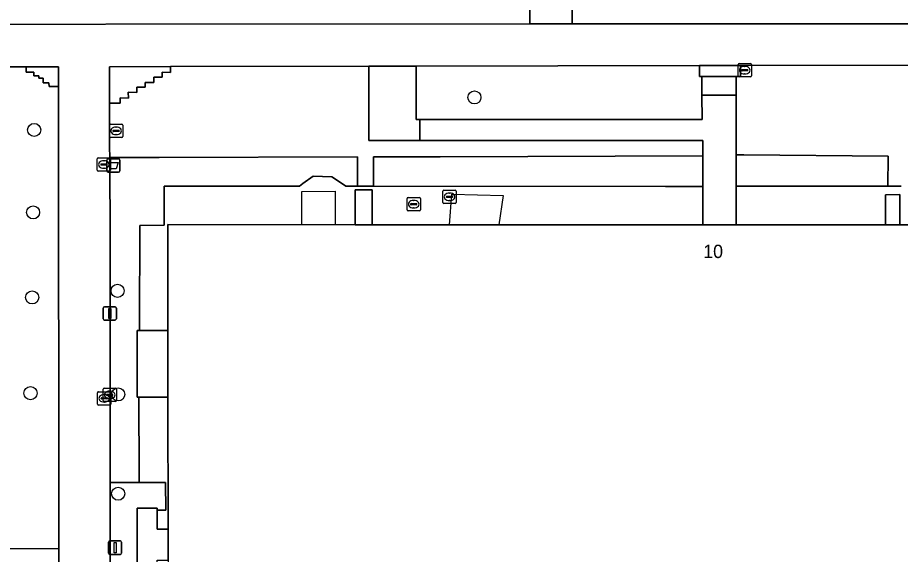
# Model space of a CAD drawing. Extents: x 161477 to 163040, y 383680 to 384871.
# Drawn here: x 161860.2 to 161926.3, y 384151.2 to 384191.4 of the extents above; entities that cross this region are included whole.
import ezdxf

# ---------------------------------------------------------------- set-up
doc = ezdxf.new("R2010")
doc.units = 0
for name, color, linetype in [('IMGEO_Afvalbak', 7, 'Continuous'), ('IMGEO_Boom', 7, 'Continuous'), ('IMGEO_Groenvoorziening', 7, 'Continuous'), ('IMGEO_Hek', 7, 'Continuous'), ('IMGEO_Kolk', 7, 'Continuous'), ('IMGEO_Lichtmast', 7, 'Continuous'), ('IMGEO_Pand', 7, 'Continuous'), ('IMGEO_Pand_nummerreeks', 7, 'Continuous'), ('IMGEO_Rioolput', 7, 'Continuous'), ('IMGEO_Terreindeel_onvherhard', 7, 'Continuous'), ('IMGEO_Voetpad_gesloten', 7, 'Continuous'), ('IMGEO_Voetpad_halfverhard', 7, 'Continuous'), ('IMGEO_Voetpad_op_trap', 7, 'Continuous'), ('IMGEO_Voetpad_open', 7, 'Continuous')]:
    doc.layers.add(name, color=color, linetype=linetype)

msp = doc.modelspace()

# ---------------------------------------------------------------- linework, layer by layer
at = {"layer": 'IMGEO_Afvalbak'}
for p, q in [((161866.835, 384179.91), (161866.835, 384180.71)), ((161866.835, 384180.71), (161866.835, 384179.91)), ((161866.935, 384180.81), (161867.725, 384180.81)), ((161867.725, 384180.81), (161866.935, 384180.81)), ((161867.825, 384180.71), (161867.825, 384179.91)), ((161867.825, 384179.91), (161867.825, 384180.71)), ((161867.725, 384179.81), (161866.935, 384179.81)), ((161866.935, 384179.81), (161867.725, 384179.81))]:
    msp.add_line(p, q, dxfattribs=at)
msp.add_lwpolyline([(161866.978, 384180.524), (161867.682, 384180.524), (161867.533, 384180.054), (161867.127, 384180.054), (161866.978, 384180.524)], dxfattribs=at)
for centre, start, end in [((161866.935, 384180.71), 90, 180), ((161866.935, 384180.71), 90, 180), ((161867.725, 384180.71), 0, 90), ((161867.725, 384180.71), 360, 90), ((161866.935, 384179.91), 180, 270), ((161866.935, 384179.91), 180, 270), ((161867.725, 384179.91), 270, 0), ((161867.725, 384179.91), 270, 0)]:
    msp.add_arc(centre, 0.1, start, end, dxfattribs=at)
at = {"layer": 'IMGEO_Boom'}
for centre in [(161894.4, 384185.41), (161861.392, 384182.972), (161861.316, 384176.797), (161867.643, 384170.917), (161861.243, 384170.422), (161861.119, 384163.251), (161867.69, 384163.158), (161867.69, 384155.716)]:
    msp.add_circle(centre, 0.489, dxfattribs=at)
at = {"layer": 'IMGEO_Groenvoorziening'}
for points in [[(161959.935, 384200.23), (161959.929, 384200.954), (161957.522, 384200.994), (161947.488, 384200.994), (161945.032, 384200.994), (161928.988, 384200.994), (161928.988, 384218.997), (161901.724, 384218.997), (161901.724, 384190.932), (161937.431, 384190.919), (161950.369, 384190.922), (161959.829, 384191.078), (161959.943, 384199.331)], [(161898.56, 384203.307), (161831.783, 384203.307), (161831.783, 384192.925), (161832.53, 384192.925), (161832.53, 384192.317), (161833.278, 384192.317), (161833.278, 384191.865), (161834.073, 384191.865), (161834.073, 384191.46), (161834.915, 384191.46), (161834.916, 384190.882), (161898.56, 384190.919)], [(161886.491, 384187.746), (161871.621, 384187.719), (161871.622, 384187.289), (161870.989, 384187.298), (161870.979, 384186.925), (161870.359, 384186.923), (161870.354, 384186.531), (161869.725, 384186.534), (161869.723, 384186.17), (161869.097, 384186.168), (161869.103, 384185.781), (161868.448, 384185.792), (161868.469, 384185.36), (161867.843, 384185.37), (161867.839, 384184.989), (161867.046, 384184.991), (161867.053, 384181.699), (161867.055, 384180.903), (161870.771, 384180.913), (161885.628, 384180.952), (161885.628, 384178.755), (161886.844, 384178.76), (161886.844, 384180.955), (161891.838, 384180.969), (161911.527, 384181.021), (161911.527, 384182.179), (161890.318, 384182.179), (161886.493, 384182.179)], [(161911.445, 384186.981), (161911.288, 384186.981), (161911.288, 384187.79), (161890.029, 384187.752), (161890.031, 384183.761), (161890.321, 384183.757), (161911.485, 384183.749), (161911.462, 384185.585)], [(161911.527, 384181.021), (161891.838, 384180.969), (161886.844, 384180.955), (161886.844, 384178.76), (161908.738, 384178.74), (161911.526, 384178.737)], [(161925.428, 384181.007), (161914.591, 384181.113), (161914.03, 384181.119), (161914.029, 384178.754), (161917.259, 384178.754), (161925.397, 384178.753)], [(161869.117, 384167.939), (161869.285, 384167.939), (161869.286, 384168.262), (161869.315, 384175.802), (161871.142, 384175.827), (161871.142, 384178.767), (161881.283, 384178.758), (161881.537, 384178.948), (161882.306, 384179.521), (161883.718, 384179.459), (161884.289, 384179.076), (161884.766, 384178.755), (161885.628, 384178.755), (161885.628, 384180.952), (161870.771, 384180.913), (161867.055, 384180.903), (161867.055, 384180.764), (161867.078, 384179.395), (161867.081, 384176.171), (161867.101, 384156.591), (161867.101, 384156.554), (161869.229, 384156.554), (161869.266, 384156.554), (161869.263, 384157.915), (161869.253, 384162.172), (161869.251, 384162.956), (161869.107, 384162.957)]]:
    msp.add_lwpolyline(points, close=True, dxfattribs=at)
for points in [[(161856.034, 384151.593), (161863.239, 384151.611), (161863.207, 384185.898), (161863.207, 384186.237), (161862.507, 384186.237), (161862.492, 384186.514), (161862.065, 384186.514), (161862.065, 384186.863), (161861.737, 384186.863), (161861.737, 384187.027), (161861.378, 384187.027), (161861.378, 384187.314), (161860.783, 384187.314), (161860.783, 384187.71), (161852.453, 384187.71)], [(161942.475, 384187.845), (161914.35, 384187.795), (161914.35, 384186.981), (161914.032, 384186.981), (161914.032, 384185.585), (161914.03, 384181.119), (161914.591, 384181.113), (161925.428, 384181.007), (161925.397, 384178.753), (161926.399, 384178.767)]]:
    msp.add_lwpolyline(points, dxfattribs=at)
at = {"layer": 'IMGEO_Hek'}
for points in [[(161881.458, 384178.371), (161883.959, 384178.376)], [(161881.458, 384175.876), (161881.458, 384178.371)], [(161883.959, 384178.376), (161883.959, 384175.876)], [(161892.524, 384175.874), (161892.708, 384178.17)], [(161892.708, 384178.17), (161896.552, 384178.063)], [(161896.552, 384178.063), (161896.239, 384175.874)]]:
    msp.add_lwpolyline(points, dxfattribs=at)
at = {"layer": 'IMGEO_Kolk'}
for p, q in [((161914.169, 384187.024), (161914.169, 384187.876)), ((161914.244, 384187.95), (161915.096, 384187.95)), ((161914.657, 384187.73), (161914.682, 384187.73)), ((161915.17, 384187.876), (161915.17, 384187.024)), ((161915.096, 384186.95), (161914.244, 384186.95)), ((161914.428, 384187.444), (161914.428, 384187.456)), ((161914.866, 384187.407), (161914.468, 384187.407)), ((161914.471, 384187.493), (161914.869, 384187.493)), ((161914.68, 384187.17), (161914.655, 384187.17)), ((161914.912, 384187.456), (161914.912, 384187.444)), ((161867.036, 384182.483), (161867.036, 384183.335)), ((161867.111, 384183.409), (161867.963, 384183.409)), ((161867.338, 384182.952), (161867.736, 384182.952)), ((161867.524, 384183.189), (161867.549, 384183.189)), ((161868.037, 384183.335), (161868.037, 384182.483)), ((161867.963, 384182.409), (161867.111, 384182.409)), ((161867.295, 384182.903), (161867.295, 384182.915)), ((161867.733, 384182.866), (161867.335, 384182.866)), ((161867.547, 384182.629), (161867.522, 384182.629)), ((161867.779, 384182.915), (161867.779, 384182.903)), ((161866.121, 384179.958), (161866.121, 384180.81)), ((161866.196, 384180.884), (161867.048, 384180.884)), ((161866.38, 384180.378), (161866.38, 384180.39)), ((161866.818, 384180.341), (161866.42, 384180.341)), ((161866.423, 384180.427), (161866.821, 384180.427)), ((161866.609, 384180.664), (161866.634, 384180.664)), ((161866.864, 384180.39), (161866.864, 384180.378)), ((161867.122, 384180.81), (161867.122, 384179.958)), ((161867.048, 384179.884), (161866.196, 384179.884)), ((161866.632, 384180.104), (161866.607, 384180.104)), ((161866.147, 384162.433), (161866.147, 384163.285)), ((161866.222, 384163.359), (161867.074, 384163.359)), ((161866.56, 384162.694), (161866.56, 384163.546)), ((161866.635, 384163.62), (161867.487, 384163.62)), ((161866.635, 384163.139), (161866.66, 384163.139)), ((161866.819, 384163.114), (161866.819, 384163.126)), ((161866.862, 384163.163), (161867.26, 384163.163)), ((161867.048, 384163.4), (161867.073, 384163.4)), ((161867.148, 384163.285), (161867.148, 384162.433)), ((161867.303, 384163.126), (161867.303, 384163.114)), ((161867.561, 384163.546), (161867.561, 384162.694)), ((161866.406, 384162.853), (161866.406, 384162.865)), ((161866.844, 384162.816), (161866.446, 384162.816)), ((161866.449, 384162.902), (161866.847, 384162.902)), ((161866.658, 384162.579), (161866.633, 384162.579)), ((161867.487, 384162.62), (161866.635, 384162.62)), ((161867.257, 384163.077), (161866.859, 384163.077)), ((161866.89, 384162.865), (161866.89, 384162.853)), ((161867.071, 384162.84), (161867.046, 384162.84)), ((161867.074, 384162.359), (161866.222, 384162.359))]:
    msp.add_line(p, q, dxfattribs=at)
for points in [[(161914.169, 384187.024), (161914.169, 384187.876)], [(161914.244, 384187.95), (161915.096, 384187.95)], [(161915.17, 384187.876), (161915.17, 384187.024)], [(161915.096, 384186.95), (161914.244, 384186.95)], [(161867.036, 384182.483), (161867.036, 384183.335)], [(161867.111, 384183.409), (161867.963, 384183.409)], [(161868.037, 384183.335), (161868.037, 384182.483)], [(161867.963, 384182.409), (161867.111, 384182.409)], [(161866.121, 384179.958), (161866.121, 384180.81)], [(161866.196, 384180.884), (161867.048, 384180.884)], [(161867.122, 384180.81), (161867.122, 384179.958)], [(161867.048, 384179.884), (161866.196, 384179.884)], [(161866.147, 384162.433), (161866.147, 384163.285)], [(161866.222, 384163.359), (161867.074, 384163.359)], [(161866.56, 384162.694), (161866.56, 384163.546)], [(161866.635, 384163.62), (161867.487, 384163.62)], [(161867.148, 384163.285), (161867.148, 384162.433)], [(161867.561, 384163.546), (161867.561, 384162.694)], [(161867.487, 384162.62), (161866.635, 384162.62)], [(161867.074, 384162.359), (161866.222, 384162.359)]]:
    msp.add_lwpolyline(points, dxfattribs=at)
for centre, radius, start, end in [((161914.246, 384187.874), 0.0765, 91.55205, 178.44795), ((161914.246, 384187.874), 0.0765, 91.55205, 178.44795), ((161915.094, 384187.874), 0.0765, 1.55205, 88.44795), ((161915.094, 384187.874), 0.0765, 1.55205, 88.44795), ((161914.246, 384187.026), 0.0765, 181.55205, 268.44795), ((161914.246, 384187.026), 0.0765, 181.55205, 268.44795), ((161914.468, 384187.453), 0.0403, 85.87752, 175.75265), ((161914.465, 384187.443), 0.0366, 178.93798, 274.71019), ((161914.869, 384187.45), 0.043, 264.86636, 352.45326), ((161914.873, 384187.455), 0.0386, 1.73085, 96.63898), ((161915.094, 384187.026), 0.0765, 271.55205, 358.44795), ((161915.094, 384187.026), 0.0765, 271.55205, 358.44795), ((161867.113, 384183.333), 0.0765, 91.55205, 178.44795), ((161867.113, 384183.333), 0.0765, 91.55205, 178.44795), ((161867.335, 384182.912), 0.0403, 85.87752, 175.75265), ((161867.74, 384182.914), 0.0386, 1.73085, 96.63898), ((161867.961, 384183.333), 0.0765, 1.55205, 88.44795), ((161867.961, 384183.333), 0.0765, 1.55205, 88.44795), ((161867.113, 384182.485), 0.0765, 181.55205, 268.44795), ((161867.113, 384182.485), 0.0765, 181.55205, 268.44795), ((161867.332, 384182.902), 0.0366, 178.93798, 274.71019), ((161867.736, 384182.909), 0.043, 264.86636, 352.45326), ((161867.961, 384182.485), 0.0765, 271.55205, 358.44795), ((161867.961, 384182.485), 0.0765, 271.55205, 358.44795), ((161866.198, 384180.808), 0.0765, 91.55205, 178.44795), ((161866.198, 384180.808), 0.0765, 91.55205, 178.44795), ((161866.42, 384180.387), 0.0403, 85.87752, 175.75265), ((161866.417, 384180.377), 0.0366, 178.93798, 274.71019), ((161866.821, 384180.384), 0.043, 264.86636, 352.45326), ((161866.825, 384180.389), 0.0386, 1.73085, 96.63898), ((161867.046, 384180.808), 0.0765, 1.55205, 88.44795), ((161867.046, 384180.808), 0.0765, 1.55205, 88.44795), ((161866.198, 384179.96), 0.0765, 181.55205, 268.44795), ((161866.198, 384179.96), 0.0765, 181.55205, 268.44795), ((161867.046, 384179.96), 0.0765, 271.55205, 358.44795), ((161867.046, 384179.96), 0.0765, 271.55205, 358.44795), ((161866.224, 384163.283), 0.0765, 91.55205, 178.44795), ((161866.224, 384163.283), 0.0765, 91.55205, 178.44795), ((161866.637, 384163.544), 0.0765, 91.55205, 178.44795), ((161866.637, 384163.544), 0.0765, 91.55205, 178.44795), ((161866.859, 384163.123), 0.0403, 85.87752, 175.75265), ((161866.856, 384163.113), 0.0366, 178.93798, 274.71019), ((161867.072, 384163.283), 0.0765, 1.55205, 88.44795), ((161867.072, 384163.283), 0.0765, 1.55205, 88.44795), ((161867.26, 384163.12), 0.043, 264.86636, 352.45326), ((161867.264, 384163.125), 0.0386, 1.73085, 96.63898), ((161867.485, 384163.544), 0.0765, 1.55205, 88.44795), ((161867.485, 384163.544), 0.0765, 1.55205, 88.44795), ((161866.224, 384162.435), 0.0765, 181.55205, 268.44795), ((161866.224, 384162.435), 0.0765, 181.55205, 268.44795), ((161866.446, 384162.862), 0.0403, 85.87752, 175.75265), ((161866.443, 384162.852), 0.0366, 178.93798, 274.71019), ((161866.637, 384162.696), 0.0765, 181.55205, 268.44795), ((161866.637, 384162.696), 0.0765, 181.55205, 268.44795), ((161866.847, 384162.859), 0.043, 264.86636, 352.45326), ((161866.851, 384162.864), 0.0386, 1.73085, 96.63898), ((161867.072, 384162.435), 0.0765, 271.55205, 358.44795), ((161867.072, 384162.435), 0.0765, 271.55205, 358.44795), ((161867.485, 384162.696), 0.0765, 271.55205, 358.44795), ((161867.485, 384162.696), 0.0765, 271.55205, 358.44795)]:
    msp.add_arc(centre, radius, start, end, dxfattribs=at)
for centre, major_axis, ratio, start_param, end_param in [((161914.656, 384187.45), (-0.387, 0.002), 0.722429, 4.712389, 7.853982), ((161914.681, 384187.45), (-0.39, 0.002), 0.717154, 1.570796, 4.712389), ((161867.523, 384182.909), (-0.387, 0.002), 0.722429, 4.712389, 7.853982), ((161867.548, 384182.909), (-0.39, 0.002), 0.717154, 1.570796, 4.712389), ((161866.608, 384180.384), (-0.387, 0.002), 0.722429, 4.712389, 7.853982), ((161866.633, 384180.384), (-0.39, 0.002), 0.717154, 1.570796, 4.712389), ((161866.634, 384162.859), (-0.387, 0.002), 0.722429, 4.712389, 7.853982), ((161866.659, 384162.859), (-0.39, 0.002), 0.717154, 1.570796, 4.712389), ((161867.047, 384163.12), (-0.387, 0.002), 0.722429, 4.712389, 7.853982), ((161867.072, 384163.12), (-0.39, 0.002), 0.717154, 1.570796, 4.712389)]:
    msp.add_ellipse(centre, major_axis=major_axis, ratio=ratio, start_param=start_param, end_param=end_param, dxfattribs=at)
at = {"layer": 'IMGEO_Lichtmast'}
for p, q in [((161866.665, 384169.73), (161867.455, 384169.73)), ((161867.455, 384169.73), (161866.665, 384169.73)), ((161866.565, 384168.83), (161866.565, 384169.63)), ((161866.565, 384169.63), (161866.565, 384168.83)), ((161867.555, 384169.63), (161867.555, 384168.83)), ((161867.555, 384168.83), (161867.555, 384169.63)), ((161867.455, 384168.73), (161866.665, 384168.73)), ((161866.665, 384168.73), (161867.455, 384168.73)), ((161866.962, 384151.272), (161866.962, 384152.072)), ((161866.962, 384152.072), (161866.962, 384151.272)), ((161867.062, 384152.172), (161867.852, 384152.172)), ((161867.852, 384152.172), (161867.062, 384152.172)), ((161867.952, 384152.072), (161867.952, 384151.272)), ((161867.952, 384151.272), (161867.952, 384152.072)), ((161867.852, 384151.172), (161867.062, 384151.172)), ((161867.062, 384151.172), (161867.852, 384151.172))]:
    msp.add_line(p, q, dxfattribs=at)
for points in [[(161866.985, 384169.605), (161867.135, 384169.605), (161867.135, 384168.855), (161866.985, 384168.855), (161866.985, 384169.605)], [(161867.382, 384152.047), (161867.532, 384152.047), (161867.532, 384151.297), (161867.382, 384151.297), (161867.382, 384152.047)]]:
    msp.add_lwpolyline(points, dxfattribs=at)
for centre, start, end in [((161866.665, 384169.63), 90, 180), ((161866.665, 384169.63), 90, 180), ((161867.455, 384169.63), 0, 90), ((161867.455, 384169.63), 360, 90), ((161866.665, 384168.83), 180, 270), ((161866.665, 384168.83), 180, 270), ((161867.455, 384168.83), 270, 0), ((161867.455, 384168.83), 270, 0), ((161867.062, 384152.072), 90, 180), ((161867.062, 384152.072), 90, 180), ((161867.852, 384152.072), 0, 90), ((161867.852, 384152.072), 360, 90), ((161867.062, 384151.272), 180, 270), ((161867.062, 384151.272), 180, 270), ((161867.852, 384151.272), 270, 0), ((161867.852, 384151.272), 270, 0)]:
    msp.add_arc(centre, 0.1, start, end, dxfattribs=at)
at = {"layer": 'IMGEO_Pand'}
msp.add_lwpolyline([(161945.027, 384175.873), (161926.299, 384175.874), (161925.232, 384175.874), (161914.028, 384175.874), (161911.525, 384175.874), (161886.732, 384175.875), (161885.455, 384175.875), (161871.412, 384175.876), (161871.419, 384168.026), (161871.419, 384167.933), (161871.423, 384163.067), (161871.423, 384162.958), (161871.432, 384153.064), (161871.434, 384150.746), (161871.439, 384144.431), (161871.441, 384142.039), (161871.446, 384136.601), (161876.803, 384136.603), (161879.273, 384136.604), (161919.889, 384136.62), (161935.366, 384136.609)], dxfattribs=at)
at = {"layer": 'IMGEO_Rioolput'}
for p, q in [((161892.039, 384177.534), (161892.039, 384178.386)), ((161892.114, 384178.46), (161892.966, 384178.46)), ((161893.04, 384178.386), (161893.04, 384177.534)), ((161889.349, 384176.984), (161889.349, 384177.836)), ((161889.424, 384177.91), (161890.276, 384177.91)), ((161889.837, 384177.69), (161889.862, 384177.69)), ((161890.35, 384177.836), (161890.35, 384176.984)), ((161892.298, 384177.954), (161892.298, 384177.966)), ((161892.736, 384177.917), (161892.338, 384177.917)), ((161892.341, 384178.003), (161892.739, 384178.003)), ((161892.55, 384177.68), (161892.525, 384177.68)), ((161892.527, 384178.24), (161892.552, 384178.24)), ((161892.782, 384177.966), (161892.782, 384177.954)), ((161889.608, 384177.404), (161889.608, 384177.416)), ((161890.046, 384177.367), (161889.648, 384177.367)), ((161889.651, 384177.453), (161890.049, 384177.453)), ((161889.86, 384177.13), (161889.835, 384177.13)), ((161890.092, 384177.416), (161890.092, 384177.404)), ((161892.966, 384177.46), (161892.114, 384177.46)), ((161890.276, 384176.91), (161889.424, 384176.91))]:
    msp.add_line(p, q, dxfattribs=at)
for points in [[(161892.039, 384177.534), (161892.039, 384178.386)], [(161892.114, 384178.46), (161892.966, 384178.46)], [(161893.04, 384178.386), (161893.04, 384177.534)], [(161889.349, 384176.984), (161889.349, 384177.836)], [(161889.424, 384177.91), (161890.276, 384177.91)], [(161890.35, 384177.836), (161890.35, 384176.984)], [(161892.966, 384177.46), (161892.114, 384177.46)], [(161890.276, 384176.91), (161889.424, 384176.91)]]:
    msp.add_lwpolyline(points, dxfattribs=at)
for centre, radius, start, end in [((161892.116, 384178.384), 0.0765, 91.55205, 178.44795), ((161892.116, 384178.384), 0.0765, 91.55205, 178.44795), ((161892.964, 384178.384), 0.0765, 1.55205, 88.44795), ((161892.964, 384178.384), 0.0765, 1.55205, 88.44795), ((161889.426, 384177.834), 0.0765, 91.55205, 178.44795), ((161889.426, 384177.834), 0.0765, 91.55205, 178.44795), ((161890.274, 384177.834), 0.0765, 1.55205, 88.44795), ((161890.274, 384177.834), 0.0765, 1.55205, 88.44795), ((161892.338, 384177.963), 0.0403, 85.87752, 175.75265), ((161892.335, 384177.953), 0.0366, 178.93798, 274.71019), ((161892.739, 384177.96), 0.043, 264.86636, 352.45326), ((161892.743, 384177.965), 0.0386, 1.73085, 96.63898), ((161889.648, 384177.413), 0.0403, 85.87752, 175.75265), ((161889.645, 384177.403), 0.0366, 178.93798, 274.71019), ((161890.049, 384177.41), 0.043, 264.86636, 352.45326), ((161890.053, 384177.415), 0.0386, 1.73085, 96.63898), ((161892.116, 384177.536), 0.0765, 181.55205, 268.44795), ((161892.116, 384177.536), 0.0765, 181.55205, 268.44795), ((161892.964, 384177.536), 0.0765, 271.55205, 358.44795), ((161892.964, 384177.536), 0.0765, 271.55205, 358.44795), ((161889.426, 384176.986), 0.0765, 181.55205, 268.44795), ((161889.426, 384176.986), 0.0765, 181.55205, 268.44795), ((161890.274, 384176.986), 0.0765, 271.55205, 358.44795), ((161890.274, 384176.986), 0.0765, 271.55205, 358.44795)]:
    msp.add_arc(centre, radius, start, end, dxfattribs=at)
for centre, major_axis, ratio, start_param, end_param in [((161889.836, 384177.41), (-0.387, 0.002), 0.722429, 4.712389, 7.853982), ((161889.861, 384177.41), (-0.39, 0.002), 0.717154, 1.570796, 4.712389), ((161892.526, 384177.96), (-0.387, 0.002), 0.722429, 4.712389, 7.853982), ((161892.551, 384177.96), (-0.39, 0.002), 0.717154, 1.570796, 4.712389)]:
    msp.add_ellipse(centre, major_axis=major_axis, ratio=ratio, start_param=start_param, end_param=end_param, dxfattribs=at)
at = {"layer": 'IMGEO_Terreindeel_onvherhard'}
for points in [[(161911.526, 384178.737), (161908.738, 384178.74), (161886.844, 384178.76), (161885.628, 384178.755), (161884.766, 384178.755), (161884.289, 384179.076), (161883.718, 384179.459), (161882.306, 384179.521), (161881.537, 384178.948), (161881.283, 384178.758), (161871.142, 384178.767), (161871.142, 384175.827), (161869.315, 384175.802), (161869.286, 384168.262), (161869.285, 384167.939), (161871.419, 384167.933), (161871.419, 384168.026), (161871.412, 384175.876), (161885.455, 384175.875), (161885.457, 384176.515), (161885.465, 384178.486), (161886.742, 384178.486), (161886.735, 384176.518), (161886.732, 384175.875), (161911.525, 384175.874)], [(161871.423, 384162.958), (161870.207, 384162.952), (161869.251, 384162.956), (161869.253, 384162.172), (161869.263, 384157.915), (161869.266, 384156.554), (161871.252, 384156.555), (161871.253, 384154.482), (161870.611, 384154.478), (161870.614, 384153.062), (161871.432, 384153.064)]]:
    msp.add_lwpolyline(points, close=True, dxfattribs=at)
msp.add_lwpolyline([(161926.399, 384178.767), (161925.397, 384178.753), (161917.259, 384178.754), (161914.029, 384178.754), (161914.028, 384175.874), (161925.232, 384175.874), (161925.233, 384176.583), (161925.235, 384178.123), (161926.302, 384178.134), (161926.3, 384176.585), (161926.299, 384175.874), (161945.027, 384175.873)], dxfattribs=at)
at = {"layer": 'IMGEO_Voetpad_gesloten'}
msp.add_lwpolyline([(161871.419, 384167.933), (161869.285, 384167.939), (161869.117, 384167.939), (161869.107, 384162.957), (161869.251, 384162.956), (161870.207, 384162.952), (161871.423, 384162.958), (161871.423, 384163.067)], close=True, dxfattribs=at)
at = {"layer": 'IMGEO_Voetpad_halfverhard'}
for points in [[(161863.207, 384187.71), (161860.783, 384187.71), (161860.783, 384187.314), (161861.378, 384187.314), (161861.378, 384187.027), (161861.737, 384187.027), (161861.737, 384186.863), (161862.065, 384186.863), (161862.065, 384186.514), (161862.492, 384186.514), (161862.507, 384186.237), (161863.207, 384186.237)], [(161863.239, 384151.611), (161856.034, 384151.593), (161855.992, 384155.169), (161846.414, 384155.222), (161846.399, 384145.662), (161855.978, 384145.626), (161856.031, 384149.227), (161863.247, 384149.196)]]:
    msp.add_lwpolyline(points, close=True, dxfattribs=at)
at = {"layer": 'IMGEO_Voetpad_op_trap'}
for points in [[(161914.032, 384186.981), (161913.96, 384186.981), (161911.445, 384186.981), (161911.462, 384185.585), (161914.032, 384185.585)], [(161886.742, 384178.486), (161885.465, 384178.486), (161885.457, 384176.515), (161885.455, 384175.875), (161886.732, 384175.875), (161886.735, 384176.518)], [(161926.302, 384178.134), (161925.235, 384178.123), (161925.233, 384176.583), (161925.232, 384175.874), (161926.299, 384175.874), (161926.3, 384176.585)]]:
    msp.add_lwpolyline(points, close=True, dxfattribs=at)
at = {"layer": 'IMGEO_Voetpad_open'}
for points in [[(161898.56, 384203.307), (161898.56, 384190.919), (161901.724, 384190.932), (161901.724, 384218.997)], [(161959.943, 384199.331), (161959.829, 384191.078), (161950.369, 384190.922), (161937.431, 384190.919), (161901.724, 384190.932), (161898.56, 384190.919), (161834.916, 384190.882)], [(161852.453, 384187.71), (161860.783, 384187.71), (161863.207, 384187.71), (161863.207, 384186.237), (161863.207, 384185.898), (161863.239, 384151.611), (161863.247, 384149.196), (161863.257, 384144.435), (161863.262, 384142.045), (161863.289, 384128.521), (161844.945, 384128.623)], [(161858.546, 384119.067), (161867.138, 384119.099), (161867.115, 384142.042), (161867.113, 384144.433), (161867.101, 384156.554), (161867.101, 384156.591), (161867.081, 384176.171), (161867.078, 384179.395), (161867.055, 384180.764), (161867.055, 384180.903), (161867.053, 384181.699), (161867.046, 384184.991), (161867.041, 384187.711), (161871.621, 384187.719), (161886.491, 384187.746), (161890.029, 384187.752), (161911.288, 384187.79), (161911.343, 384187.79), (161914.35, 384187.795), (161942.475, 384187.845)], [(161869.141, 384144.432), (161869.122, 384154.637), (161870.61, 384154.629), (161870.611, 384154.478), (161871.253, 384154.482), (161871.252, 384156.555), (161869.266, 384156.554), (161869.229, 384156.554), (161867.101, 384156.554), (161867.113, 384144.433)]]:
    msp.add_lwpolyline(points, dxfattribs=at)
for points in [[(161870.359, 384186.923), (161870.979, 384186.925), (161870.989, 384187.298), (161871.622, 384187.289), (161871.621, 384187.719), (161867.041, 384187.711), (161867.046, 384184.991), (161867.839, 384184.989), (161867.843, 384185.37), (161868.469, 384185.36), (161868.448, 384185.792), (161869.103, 384185.781), (161869.097, 384186.168), (161869.723, 384186.17), (161869.725, 384186.534), (161870.354, 384186.531)], [(161890.029, 384187.752), (161886.491, 384187.746), (161886.493, 384182.179), (161890.318, 384182.179), (161890.321, 384183.757), (161890.031, 384183.761)], [(161914.35, 384187.795), (161911.343, 384187.79), (161911.288, 384187.79), (161911.288, 384186.981), (161911.445, 384186.981), (161913.96, 384186.981), (161914.032, 384186.981), (161914.35, 384186.981)], [(161914.032, 384185.585), (161911.462, 384185.585), (161911.485, 384183.749), (161890.321, 384183.757), (161890.318, 384182.179), (161911.527, 384182.179), (161911.527, 384181.021), (161911.526, 384178.737), (161911.525, 384175.874), (161914.028, 384175.874), (161914.029, 384178.754), (161914.03, 384181.119)], [(161870.622, 384150.744), (161871.434, 384150.746), (161871.432, 384153.064), (161870.614, 384153.062), (161870.611, 384154.478), (161870.61, 384154.629), (161869.122, 384154.637), (161869.141, 384144.432), (161869.146, 384142.041), (161869.156, 384136.694), (161870.663, 384136.694), (161870.647, 384142.04), (161870.64, 384144.431)]]:
    msp.add_lwpolyline(points, close=True, dxfattribs=at)

# ---------------------------------------------------------------- texts
at = {"layer": 'IMGEO_Pand_nummerreeks'}
msp.add_text('10', height=1, dxfattribs=at).set_placement((161911.555, 384173.374))

doc.saveas('drawing.dxf')
